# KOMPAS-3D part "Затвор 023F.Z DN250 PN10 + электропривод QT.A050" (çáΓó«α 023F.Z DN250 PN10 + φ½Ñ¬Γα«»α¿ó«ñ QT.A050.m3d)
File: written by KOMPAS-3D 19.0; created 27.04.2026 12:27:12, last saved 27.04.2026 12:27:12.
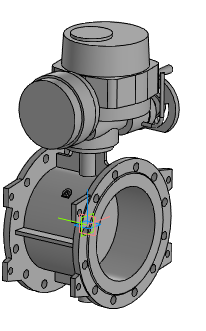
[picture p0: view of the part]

Document properties: Полное имя файла: Затвор 023F.Z DN250 PN10 + электропривод QT.A050.a3d

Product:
- Part/product: Затвор 023F.Z DN250 PN10 + электропривод QT.A050
    Масса: 170.172

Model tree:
1. Операция без истории:1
